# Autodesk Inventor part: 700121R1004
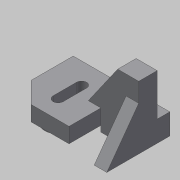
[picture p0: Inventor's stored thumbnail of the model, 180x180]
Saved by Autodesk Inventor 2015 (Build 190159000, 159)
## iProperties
Created: 2020-01
Part Number: 700121R1004
Material: 일반
Document SubType Name: Modeling
Designer: H06
Density: 1 g/cm^3
Appearance: 기본값
Author: H06
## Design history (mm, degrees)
sketch "스케치1"
  geometry: L1 (-35, 53)-(80, 53); L2 (80, 53)-(80, 16); L3 (35, -22)-(-10, -22); L4 (-35, 3)-(-35, 53); L5 (35, -22)-(35, 16); L6 (35, 16)-(80, 16); L7 (65, 16)-(80, 16); L8 (80, 16)-(80, -22); L9 (80, -22)-(65, -22); L10 (65, -22)-(65, 16); L11 (0, 28)-(0, 0); L12 (-6, 28)-(-6, 0); L13 (6, 0)-(6, 28); L14 (-35, 3)-(-10, -22); C1 r 10 at (0, 0); C2 r 16 at (0, 0); A1 r 6 centre (0, 28) between (6, 28) and (-6, 28); A2 r 6 centre (0, 0) between (-6, 0) and (6, 0); 2 further points
  constraints: 30 end point, 5 parallel, 4 centre point, 4 point on circle, 4 tangent, 3 coincident, 2 horizontal, 2 perpendicular, 1 midpoint, 1 vertical
  dimensions: "d0" = 20 diameter of C1; "d1" = 32 diameter of C2; "d2" = 38 distance between parallel lines of L6 L3; "d3" = 35 distance from line of L4 point (0, 0); "d4" = 53 distance from line of point (0, 0) L1; "d5" = 75 distance between parallel lines of L3 L1; "d6" = 45 distance between parallel lines of L2 L5; "d7" = 115 distance between parallel lines of L2 L4; "d8" = 15 distance between parallel lines of L8 L10; "d9" = 38 distance between parallel lines of L9 L7; "d10" = 28 distance of point (0, 0) L11.start; "d11" = 6 radius of A1; "d12" = 25 distance from line of L3.end L4; "d13" = 45 deg angle of L3 L14
extrude "돌출1" new body sketch "스케치1" distance "d14" = 60; taper "d15" = 0 deg
sketch "스케치2"
  geometry: L1 (0, 0)-(-52.303, 38); L2 (-52.303, 38)-(-60, 38); L3 (0, 38)-(-60, 38) reference; L4 (-60, 38)-(-60, 0); L5 (-60, 38)-(-60, 0) reference; L6 (-60, 0)-(0, 0); 1 further point
  constraints: 8 end point, 2 collinear, 1 perpendicular
  dimensions: "d16" = 144 deg angle of L1 L2
extrude "돌출2" cut sketch "스케치2" stored distance "d17" = 60; taper "d18" = 0 deg
extrude "돌출3" join sketch "스케치1" distance "d19" = 25; taper "d20" = 0 deg
sketch "스케치3"
  geometry: L1 (-25, 7)-(45, 7); L2 (45, 7)-(45, 0); L3 (45, 0)-(-25, 0); L4 (-25, 0)-(-25, 7); 2 further points
  constraints: 8 end point, 2 parallel, 1 coincident, 1 horizontal, 1 perpendicular
  dimensions: "d21" = 7 distance between parallel lines of L3 L1; "d22" = 70 distance between parallel lines of L2 L4
extrude "돌출4" cut sketch "스케치3" stored distance "d23" = 25; taper "d24" = 0 deg
extrude "돌출5" join sketch "스케치1" distance "d25" = 7; taper "d26" = 0 deg
sketch "스케치4"
  geometry: L1 (-6, 28)-(-6, 0) reference; L2 (6, 0)-(6, 28) reference; A1 r 6 centre (0, 28) between (6, 28) and (-6, 28) reference; A2 r 6 centre (0, 0) between (-6, 0) and (6, 0) reference; 1 further point
extrude "돌출6" cut sketch "스케치4" distance "d19" = 25; distance "d27" = 12; taper "d28" = 0 deg
sketch "스케치5"
  geometry: L1 (45, 0)-(45, 50); L2 (45, 50)-(20, 50); L3 (20, 50)-(-15.01, 0); L4 (-15.01, 0)-(45, 0); 2 further points
  constraints: 8 end point, 1 coincident, 1 horizontal, 1 parallel, 1 vertical
  dimensions: "d29" = 25 distance of L1.end L2.end; "d30" = 50 distance between parallel lines of L4 L2; "d31" = 55 deg angle of L2 L3
extrude "돌출7" join sketch "스케치5" distance "d32" = 22; taper "d33" = 0 deg
node "솔리드1"
